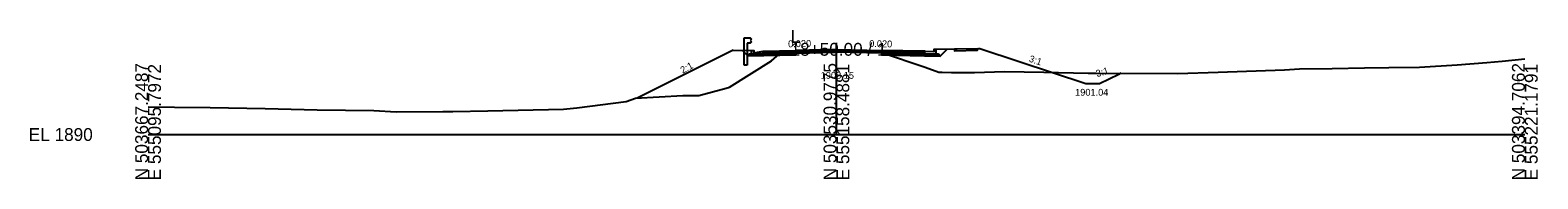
# Model space of a CAD drawing. Extents: x -26 to 4603, y -10 to 4703.
# Drawn here: x -25.7 to 302.8, y 3755.3 to 3787.8 of the extents above; entities that cross this region are included whole.
import ezdxf

# ---------------------------------------------------------------- set-up
doc = ezdxf.new("R2010")
doc.units = 0
for name, color, linetype in [('Default', 7, 'Continuous'), ('Exist Cross Section Cell', 7, 'Continuous'), ('Exist XS Ground Line', 7, 'Continuous'), ('Prop CMT Guardrail Graphics', 7, 'Continuous'), ('Prop CMT Pvmt Course 1', 7, 'Continuous'), ('Prop CMT Pvmt Course 2', 7, 'Continuous'), ('Prop CMT Pvmt Course 3', 7, 'Continuous'), ('Prop CMT Pvmt Milling', 7, 'Continuous'), ('Prop CMT Shear Line', 7, 'Continuous'), ('Prop CMT Shld Paved Course 2', 7, 'Continuous'), ('Prop CMT Shld Paved Course 3', 7, 'Continuous'), ('Prop CMT Subgrade Earthwork', 7, 'Continuous'), ('Prop Conc 4in Sidewalk', 7, 'Continuous'), ('Prop Conc Curb and Gutter', 7, 'Continuous'), ('Prop XS Ditch Slope Text', 7, 'Continuous'), ('Prop XS Finish Grade', 7, 'Continuous'), ('Prop XS Label Text', 7, 'Continuous'), ('Prop XS SS Elevation Text', 7, 'Continuous'), ('Scratch_Level_9', 7, 'Continuous')]:
    doc.layers.add(name, color=color, linetype=linetype)

msp = doc.modelspace()

# ---------------------------------------------------------------- linework, layer by layer
at = {"layer": 'Exist Cross Section Cell'}
for p, q in [((150, 3765), (150, 3785)), ((0, 3765), (150, 3765)), ((150, 3765), (300, 3765))]:
    msp.add_line(p, q, dxfattribs=at)
at = {"layer": 'Exist XS Ground Line'}
msp.add_lwpolyline([(0, 3771.07), (5.78, 3770.98), (13.53, 3770.92), (25.53, 3770.71), (36.83, 3770.37), (49.17, 3770.27), (54.05, 3769.96), (64.25, 3770), (66.39, 3770), (74.05, 3770.17), (90.51, 3770.57), (93.46, 3770.85), (104.16, 3772.21), (106.18, 3772.92), (116.51, 3773.51), (120.03, 3773.53), (125.95, 3775.1), (126.67, 3775.32), (135.85, 3781.1), (137.51, 3782.55), (140.73, 3782.97), (141.16, 3783.03), (150.04, 3783.15), (150.25, 3783.15), (159.79, 3782.93), (159.81, 3782.93), (159.81, 3782.93), (159.81, 3782.93), (169.35, 3779.67), (172.29, 3778.58), (173.01, 3778.59), (175.08, 3778.53), (178.57, 3778.52), (179.02, 3778.51), (180.11, 3778.54), (186.59, 3778.73), (195.17, 3778.61), (204.86, 3778.41), (206.56, 3778.39), (224.37, 3778.32), (233.2, 3778.58), (247.62, 3779.1), (250.89, 3779.31), (258, 3779.42), (265.09, 3779.57), (270.34, 3779.62), (277.07, 3779.74), (285.24, 3780.19), (291.7, 3780.72), (295.07, 3781.05), (300, 3781.5)], dxfattribs=at)
at = {"layer": 'Prop CMT Guardrail Graphics'}
for points in [[(129.89, 3780.11), (129.89, 3786.11)], [(129.89, 3786.11), (131.23, 3786.11), (131.5, 3785.82)], [(131.5, 3785.24), (131.23, 3784.95), (130.56, 3784.95)], [(130.56, 3784.95), (130.56, 3780.11)], [(131.5, 3785.82), (131.23, 3785.53)], [(131.23, 3785.53), (131.5, 3785.24)], [(130.56, 3780.11), (129.89, 3780.11)]]:
    msp.add_lwpolyline(points, dxfattribs=at)
at = {"layer": 'Prop CMT Pvmt Course 1'}
for points in [[(134, 3783.23), (141.16, 3783.38), (141.16, 3783.13), (141.16, 3783.13), (134, 3782.98), (134, 3782.98), (134, 3782.98), (134, 3783.23), (134, 3783.23)], [(141.16, 3783.38), (141.16, 3783.03), (141.16, 3783.03), (141.16, 3783.03), (150, 3783.15), (150, 3783.15), (150, 3783.55), (141.16, 3783.38), (141.16, 3783.38)], [(159.79, 3783.36), (159.81, 3783.36), (159.81, 3782.93), (159.81, 3782.93), (159.79, 3782.93), (159.79, 3782.93), (150.25, 3783.15), (150.25, 3783.15), (150.04, 3783.15), (150.04, 3783.15), (150, 3783.15), (150, 3783.15), (150, 3783.55), (150.04, 3783.55), (150.04, 3783.55), (150.25, 3783.55), (150.25, 3783.55), (159.79, 3783.36), (159.79, 3783.36)], [(169.22, 3783.17), (159.81, 3783.36), (159.81, 3783.11), (159.81, 3783.11), (169.22, 3782.92), (169.22, 3782.92), (169.22, 3782.92), (169.22, 3783.17), (169.22, 3783.17)]]:
    msp.add_lwpolyline(points, dxfattribs=at)
at = {"layer": 'Prop CMT Pvmt Course 2'}
for points in [[(134, 3782.98), (141.16, 3783.13), (141.16, 3782.79), (141.16, 3782.79), (134, 3782.65), (134, 3782.65), (134, 3782.65), (134, 3782.98), (134, 3782.98)], [(169.22, 3782.92), (159.81, 3783.11), (159.81, 3782.77), (159.81, 3782.77), (169.22, 3782.59), (169.22, 3782.59), (169.22, 3782.59), (169.22, 3782.92), (169.22, 3782.92)]]:
    msp.add_lwpolyline(points, dxfattribs=at)
at = {"layer": 'Prop CMT Pvmt Course 3'}
for points in [[(134, 3782.65), (141.16, 3782.79), (141.16, 3782.42), (141.16, 3782.42), (134, 3782.28), (134, 3782.28), (134, 3782.28), (134, 3782.65), (134, 3782.65)], [(169.22, 3782.59), (159.81, 3782.77), (159.81, 3782.4), (159.81, 3782.4), (169.22, 3782.21), (169.22, 3782.21), (169.22, 3782.21), (169.22, 3782.59), (169.22, 3782.59)], [(169.22, 3782.58), (169.22, 3782.21), (172.61, 3782.14), (172.23, 3782.52), (169.22, 3782.58)]]:
    msp.add_lwpolyline(points, dxfattribs=at)
at = {"layer": 'Prop CMT Pvmt Milling'}
for points in [[(141.16, 3783.03), (141.16, 3783.03), (150, 3783.15)], [(159.81, 3782.93), (159.79, 3782.93), (159.79, 3782.93), (150.25, 3783.15), (150.25, 3783.15), (150.04, 3783.15), (150.04, 3783.15), (150, 3783.15)]]:
    msp.add_lwpolyline(points, dxfattribs=at)
at = {"layer": 'Prop CMT Shld Paved Course 2'}
for points in [[(141.16, 3783.13), (141.16, 3782.79), (141.16, 3782.79), (141.16, 3782.79), (150, 3782.97), (150, 3782.97), (150, 3783.3), (141.16, 3783.13), (141.16, 3783.13)], [(159.79, 3783.11), (159.81, 3783.11), (159.81, 3782.77), (159.81, 3782.77), (159.79, 3782.77), (159.79, 3782.77), (150.25, 3782.97), (150.25, 3782.97), (150.04, 3782.97), (150.04, 3782.97), (150, 3782.97), (150, 3782.97), (150, 3783.3), (150.04, 3783.3), (150.04, 3783.3), (150.25, 3783.3), (150.25, 3783.3), (159.79, 3783.11), (159.79, 3783.11)]]:
    msp.add_lwpolyline(points, dxfattribs=at)
at = {"layer": 'Prop CMT Shld Paved Course 3'}
msp.add_lwpolyline([(131, 3782.59), (134, 3782.65), (134, 3782.28), (134, 3782.28), (130.7, 3782.21), (130.7, 3782.21), (130.7, 3782.21), (131, 3782.59), (131, 3782.59)], dxfattribs=at)
at = {"layer": 'Prop CMT Subgrade Earthwork'}
for points in [[(129.54, 3783.37), (130.7, 3782.21), (130.7, 3782.21)], [(130.7, 3782.21), (130.7, 3782.21), (141.16, 3782.42)], [(172.61, 3782.14), (172.61, 3782.14), (159.81, 3782.4)], [(169.22, 3782.21), (172.61, 3782.14), (174.06, 3783.59)]]:
    msp.add_lwpolyline(points, dxfattribs=at)
at = {"layer": 'Prop Conc 4in Sidewalk'}
msp.add_lwpolyline([(175.73, 3783.62), (175.73, 3783.29), (180.73, 3783.39), (180.73, 3783.72), (175.73, 3783.62)], dxfattribs=at)
at = {"layer": 'Prop Conc Curb and Gutter'}
for points in [[(132, 3782.83), (134, 3783.23), (134, 3782.65), (134, 3782.65), (131.5, 3782.6), (131.5, 3782.6), (131.5, 3782.6), (131.5, 3783.33), (132, 3783.33), (132, 3783.33), (132, 3782.83), (132, 3782.83), (132, 3782.83)], [(169.36, 3783.16), (169.22, 3783.17), (169.22, 3783.13), (169.22, 3782.58), (169.39, 3782.58), (171.73, 3782.53), (171.73, 3783.49), (171.73, 3783.55), (171.7, 3783.55), (171.23, 3783.55), (171.23, 3783.52), (171.22, 3783.05), (169.36, 3783.16)]]:
    msp.add_lwpolyline(points, dxfattribs=at)
at = {"layer": 'Prop XS Finish Grade'}
for points in [[(127.5, 3783.41), (106.56, 3772.94)], [(127.5, 3783.41), (131.5, 3783.33), (131.5, 3783.33)], [(204.33, 3776.04), (204.33, 3776.04), (204.33, 3776.04), (204.33, 3776.04), (189.79, 3780.88), (181.23, 3783.73), (180.95, 3783.72), (171.73, 3783.55)], [(212.01, 3778.37), (211.53, 3778.12), (207.34, 3776.04), (207.21, 3776.04), (204.33, 3776.04)]]:
    msp.add_lwpolyline(points, dxfattribs=at)
at = {"layer": 'Scratch_Level_9'}
msp.add_lwpolyline([(134, 3783.23), (134, 3782.98)], dxfattribs=at)

# ---------------------------------------------------------------- texts
at = {"layer": 'Default'}
msp.add_text('-', height=0.0001, dxfattribs=at).set_placement((0, 3765))
at = {"layer": 'Exist Cross Section Cell'}
for s, p in [('18+50.00 / 1', (140, 3782.2)), ('L', (140, 3785)), ('EL 1890', (-26, 3763.6))]:
    msp.add_text(s, height=2.8, dxfattribs=at).set_placement(p)
for s, p in [('N 503667.2487', (0, 3755)), ('E 555095.7972', (2.8, 3755)), ('N 503530.9775', (150, 3755)), ('E 555158.4881', (152.8, 3755)), ('N 503394.7062', (300, 3755)), ('E 555221.1791', (302.8, 3755))]:
    msp.add_text(s, height=2.8, rotation=90, dxfattribs=at).set_placement(p)
at = {"layer": 'Prop CMT Shear Line'}
for p in [(127.5, 3783.41), (129, 3783.38), (132, 3782.83), (134, 3783.23), (134, 3783.23), (150, 3783.55), (169.22, 3783.17), (171.22, 3783.04), (175.73, 3783.62), (180.73, 3783.72), (181.23, 3783.72), (212.01, 3778.37), (204.33, 3776.04), (108.32, 3773.04)]:
    msp.add_text('X', height=0.0025, dxfattribs=at).set_placement(p)
at = {"layer": 'Prop XS Ditch Slope Text'}
msp.add_text('1901.04', height=1.5, dxfattribs=at).set_placement((202.01, 3773.47))
at = {"layer": 'Prop XS Label Text'}
for s, rotation, p in [('0.020', 1.1458, (139.48, 3784.04)), ('0.020', 358.8542, (157.12, 3784.11)), ('3:1', 341.5958, (191.83, 3780.94)), ('2:1', 28.3986, (116.49, 3778.26)), ('3:1', 16.8512, (206.79, 3777.52))]:
    msp.add_text(s, height=1.5, rotation=rotation, dxfattribs=at).set_placement(p)
at = {"layer": 'Prop XS SS Elevation Text'}
msp.add_text('1908.15', height=1.5, dxfattribs=at).set_placement((146.57, 3777.17))

doc.saveas('drawing.dxf')
